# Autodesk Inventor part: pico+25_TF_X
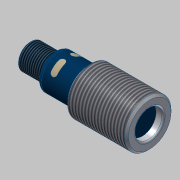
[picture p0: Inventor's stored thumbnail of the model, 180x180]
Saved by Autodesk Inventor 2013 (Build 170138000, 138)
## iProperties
Shininess: 20.0
Length Units: 11269
Angle Units: 11279
Time Units: 11290
Mass Units: 11283
Length Display Precision: 2
Angle Display Precision: 2
Part Number: pico+25_TF_X
Material: Nichtrostender Stahl - 440C
Document SubType Name: Modellieren
Description: Ipc-25 /CXX/M18
Checked By: Alves
Created: 2005-08
Designer: Ohle
Manufacturer: Standard
Standards Organization: Custom
Density: 0.0
Volumn: 0.0
Area: 0.0
PropertySet Name: Model Information
Control State: 0
Master: False
Checked Out: False
BESTELLNUMMER: Ipc-25 /CXX/M18
ME: ST
Title: Ipc Sensoren
Author: Ohle
Comments: keine Bemerkung
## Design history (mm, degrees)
sketch "Skizze10"
  geometry: L1 (-42.478, 0)-(2.222, 0); L2 (-38.478, 6.5)-(-38.478, 7.25); L3 (-45.9, 8)-(-45.9, 8); L4 (2.095, 0)-(-82, 0); L5 (-23.478, 8.25)-(-22.878, 8.85); L6 (-49.978, 6)-(-38.978, 6); L7 (-36.878, 8.25)-(-23.478, 8.25); L8 (-50.478, 4.5)-(-42.478, 4.5); L9 (-42.478, 0)-(-42.478, 4.5); L10 (-36.978, 8.25)-(-37.478, 8.25); L11 (-38.978, 6)-(-38.478, 6.5); L12 (-50.478, 5.5)-(-50.478, 4.5); L13 (-50.478, 5.5)-(-49.978, 6); L14 (-36.978, 8.25)-(-36.978, 8.15); L15 (-36.978, 8.15)-(-36.878, 8.15); L16 (-36.878, 8.15)-(-36.878, 8.25); L17 (-22.878, 8.85)-(-22.878, 10); L18 (-22.878, 10)-(-21.878, 11); L19 (-21.878, 11)-(4.722, 11); L20 (4.722, 11)-(5.722, 10); L21 (5.722, 10)-(5.722, 7.25); L22 (4.972, 6.5)-(2.222, 6.5); L23 (2.222, 6.5)-(2.222, 0); A1 r 1 centre (-37.478, 7.25) between (-37.478, 8.25) and (-38.478, 7.25); A2 r 0.75 centre (4.972, 7.25) between (4.972, 6.5) and (5.722, 7.25); 2 further points
  constraints: 46 end point, 10 parallel, 6 point on line, 5 perpendicular, 4 point on circle, 4 tangent, 2 centre point, 1 collinear, 1 horizontal
  dimensions: "d171" = 4.5 distance between parallel lines of L8 L1; "d257" = 8.25 distance between parallel lines of L4 L7; "d263" = 8.25 distance between parallel lines of L4 L10; "d266" = 12 distance from line of L2 L12.start; "d269" = 6 distance between parallel lines of L4 L6; "d290" = 0.5 horizontal distance of L6.end L2.start; "d291" = 45 deg angle of L11 L6 (derived); "d293" = 0.5 horizontal distance of L12.start L6.start; "d294" = 45 deg angle of L13 L6 (derived); "d295" = 8 distance of L8.start L8.end; "d296" = 1.5 distance of L10.start point (-38.478, 8.25); "d297" = 0.1 distance of L14.end L15.end; "d298" = 8.15 distance between parallel lines of L15 L1; "d299" = 15 distance from line of L5.start L2; "d300" = 1 radius of A1; "d340" = 0.75 radius of A2; "d341" = 11 distance between parallel lines of L4 L19; "d342" = 6.5 distance of L22.end L1.end; "d343" = 3.5 distance between parallel lines of L21 L23; "d344" = 1 horizontal distance of L19.end L20.end; "d345" = 135 deg angle of L20 L19; "d346" = 1 horizontal distance of L17.end L18.end; "d347" = 0.6 horizontal distance of L5.start L5.end; "d348" = 135 deg angle of L17 L5; "d349" = 135 deg angle of L19 L18 (derived); "d350" = 44.2 distance between parallel lines of L21 L2
revolve "Grundkörper pico+" sketch "Skizze10" stored, may be unused: angle "d168" = 90 deg
feature "Gewinde M12" dims "d174" = 10, "d175" = 0
feature "Gewinde M 22" dims "d179" = 10, "d180" = 0
workplane "Arbeitsebene1"
workplane "Arbeitsebene2"
sketch "Skizze13"
  geometry: L1 (-3.409, -3.409)-(3.61, 3.61); L2 (-3.439, 3.439)-(4.105, -4.105); L3 (-15.4, 0)-(15.4, 0) reference; C1 r 0.5 at (1.768, -1.768); C2 r 0.5 at (1.768, 1.768); C3 r 0.5 at (-1.768, 1.768); C4 r 0.5 at (-1.768, -1.768); C5 r 4.5 at (0, 0) reference; C6 r 0.5 at (0, 0); A1 r 2.5 centre (0, 0) between (-1.768, 1.768) and (1.768, 1.768); 2 further points
  constraints: 6 centre point, 6 point on line, 4 coincident, 4 end point, 4 equal radius, 4 point on circle, 1 horizontal alignment, 1 perpendicular
  dimensions: "d208" = 1 diameter of C3; "d209" = 5 diameter of A1
extrude "Pole" join sketch "Skizze13" distance "d212" = 7; taper "d213" = 0 deg
fillet "Rundung Pole" dims "d214" = 0.5
sketch "Skizze14"
  geometry: C1 r 0.5 at (0, -4.5); A1 r 4.5 centre (0, 0) between (4.435, -0.762) and (4.435, 0.762); A2 r 4.5 centre (0, 0) between (0, 4.5) and (0.499, 4.472) reference; A3 r 0.5 centre (0, 4.5) between (-0.499, 4.472) and (0.499, 4.472); 3 further points
  constraints: 9 point on circle, 3 centre point, 3 coincident, 1 horizontal alignment, 1 vertical alignment
  dimensions: "d215" = 9 diameter of A1; "d280" = 1 diameter of A3; "d330" = 1 diameter of C1
extrude "Verdrehsicherung" join sketch "Skizze14" distance "d217" = 7.9; taper "d218" = 0 deg
sketch "Skizze18"
  geometry: C1 r 7.25 at (0, 0) reference; C2 r 1 at (-8.15, 0)
  constraints: 1 centre point, 1 horizontal alignment
  dimensions: "d328" = 2 diameter of C2; "d329" = 8.15 distance of C1.centre C2.centre
extrude "Bohrung Ausrichtung" cut sketch "Skizze18" distance "d316" = 0.75; taper "d317" = 0 deg
workplane "Arbeitsebene4"
sketch "Skizze19"
  geometry: L1 (-38.478, 0)-(-30.18, 0); L2 (-34.178, -7.5)-(-34.178, -3); L3 (-31.178, -7.5)-(-31.178, -3); L4 (-31.178, 3)-(-31.178, 7.5); L5 (-34.178, 3)-(-34.178, 7.5); A1 r 1.5 centre (-32.678, 3) between (-31.178, 3) and (-34.178, 3); A2 r 1.5 centre (-32.678, -3) between (-34.178, -3) and (-31.178, -3); A3 r 1.5 centre (-32.678, 7.5) between (-31.178, 7.5) and (-34.178, 7.5); A4 r 1.5 centre (-32.678, -7.5) between (-34.178, -7.5) and (-31.178, -7.5); 4 further points; 1 other entity
  constraints: 10 end point, 8 point on circle, 8 tangent, 4 centre point, 3 equal radius, 2 vertical alignment, 1 horizontal, 2 other
  dimensions: "d319" = 3 diameter of A2; "d320" = 6 distance of A2.centre A1.centre; "d321" = 4.5 distance of A1.centre A3.centre; "d322" = 4.5 distance of A4.centre A2.centre; "d323" = 3 distance from line of A2.centre L1; "d324" = 5.8 dimension on A1.centre; "d325" = 5.8 dimension on A2.centre
feature "Prägen LED-Fenster" sketch "Skizze19" dims "d215" = 9, "d280" = 1, "d326" = 0.01, "d327" = 0
node "Volumenkörper1"
node "Volumenkörper"
node "Oberflächenkörper"
other parameters: "d10" = 14, "d73" = -35, "d130" = 0.2, "d207" = -95.5, "d318" = 8.25
